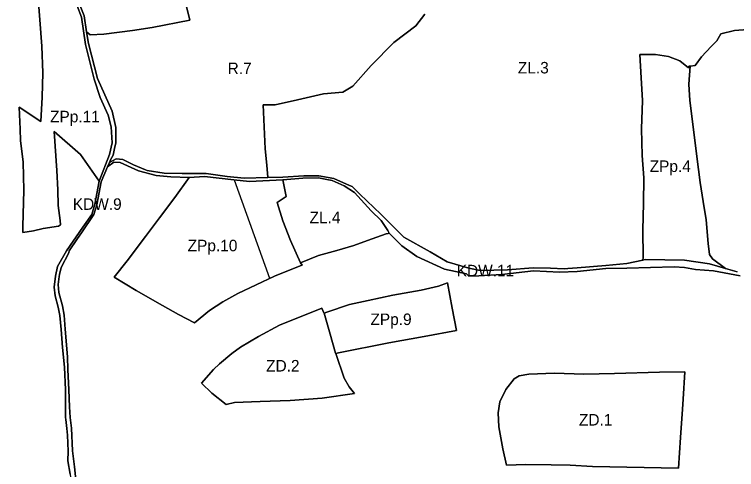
# Model space of a CAD drawing. Extents: x 7418114 to 7422197, y 5546299 to 5548348.
# Drawn here: x 7419820 to 7420446, y 5546631 to 5547025 of the extents above; entities that cross this region are included whole.
import ezdxf

# ---------------------------------------------------------------- set-up
doc = ezdxf.new("R2010")
doc.units = 0
for name, color, linetype in [('linie_lokalizacyjne', 7, 'Continuous'), ('linie_rozgraniczajace', 7, 'Continuous'), ('oznaczenia_przeznaczen', 7, 'Continuous')]:
    doc.layers.add(name, color=color, linetype=linetype)

msp = doc.modelspace()

# ---------------------------------------------------------------- linework, layer by layer
at = {"layer": 'linie_lokalizacyjne'}
msp.add_lwpolyline([(7420041.67, 5546796.53), (7420011.28, 5546881.78)], dxfattribs=at)
at = {"layer": 'linie_rozgraniczajace'}
for points in [[(7419866.28, 5547042.91), (7419867.1, 5547043.21), (7419870.32, 5547044.39), (7419873.48, 5547049.14), (7419876.24, 5547055.72), (7419880.16, 5547059.55), (7419888.8, 5547063.06), (7419894.5, 5547067.18), (7419904.63, 5547076.27), (7419916.45, 5547084.56), (7419931.62, 5547094.6), (7419938.65, 5547100.47), (7419955.53, 5547088.89), (7419972.53, 5547020.52), (7419939.92, 5547014.2), (7419922.63, 5547011.63), (7419898.04, 5547008.4), (7419885.91, 5547007.85), (7419883.01, 5547010.34), (7419880.8, 5547024.17), (7419876.89, 5547034.4), (7419869.75, 5547041.1), (7419866.28, 5547042.91)], [(7420365.05, 5546812.39), (7420365.34, 5546814.53), (7420365.13, 5546838.52), (7420365.57, 5546861.58), (7420365.75, 5546883.8), (7420364.53, 5546902.99), (7420363.96, 5546926.22), (7420364.77, 5546950.76), (7420363.7, 5546970.52), (7420362.55, 5546990.68), (7420362.55, 5546990.68), (7420376.04, 5546990.57), (7420387.25, 5546988.91), (7420397.13, 5546985.1), (7420404.49, 5546979.2), (7420404.8, 5546980.45), (7420405.91, 5546980.54), (7420404.94, 5546964.91), (7420405.7, 5546950.84), (7420408.3, 5546930.35), (7420411.7, 5546902.25), (7420414.68, 5546879.64), (7420417.29, 5546863.26), (7420419.89, 5546847.17), (7420421.68, 5546826.83), (7420422.92, 5546817.13), (7420425.35, 5546813.35), (7420436.66, 5546805.15), (7420422.78, 5546809.01), (7420401.1, 5546812.46), (7420367.15, 5546812.9)], [(7419906.72, 5546797.51), (7419918.11, 5546811.82), (7419934.13, 5546832.93), (7419946.03, 5546849.02), (7419959.33, 5546866.63), (7419971.86, 5546884.03), (7419985.08, 5546884.9), (7419997.9, 5546883.43), (7420010.56, 5546881.87), (7420024.16, 5546880.65), (7420053.14, 5546881.89), (7420055.79, 5546867.64), (7420048.26, 5546862.49), (7420053.02, 5546846.4), (7420059.76, 5546829.38), (7420068.47, 5546810.09), (7420069.64, 5546807.99), (7420068.11, 5546807.33), (7420045.91, 5546798.51), (7420013.9, 5546783.56), (7420000.99, 5546776.21), (7419989.49, 5546768.66), (7419976.35, 5546758.07), (7419962.65, 5546765.35), (7419948.77, 5546773), (7419926.05, 5546786.07)], [(7420048.26, 5546862.49), (7420055.79, 5546867.64), (7420053.14, 5546881.89), (7420070.41, 5546883.55), (7420084, 5546883.64), (7420091.09, 5546882.32), (7420095.8, 5546881.33), (7420106.07, 5546876.93), (7420115.02, 5546870.88), (7420120.94, 5546864.57), (7420129.47, 5546855.14), (7420138.36, 5546846.8), (7420143.92, 5546837.93), (7420145.2, 5546835.86), (7420144.31, 5546835.6), (7420142.44, 5546835.09), (7420126.42, 5546829.27), (7420114.42, 5546825.03), (7420099.8, 5546820.58), (7420084.05, 5546816.29), (7420068.47, 5546810.09), (7420059.76, 5546829.38), (7420053.02, 5546846.4)], [(7419982.44, 5546705.77), (7419991.49, 5546696.97), (7420003.98, 5546687.17), (7420011.2, 5546688.84), (7420033.45, 5546689.74), (7420059.41, 5546690.61), (7420087.07, 5546692.77), (7420115.22, 5546696.83), (7420110.55, 5546702.45), (7420106.29, 5546709.89), (7420098.82, 5546731.5), (7420101.35, 5546731.92), (7420144.89, 5546740.68), (7420175.41, 5546746.11), (7420203.47, 5546751.22), (7420199.7, 5546770.57), (7420195.69, 5546792.55), (7420188.04, 5546789.7), (7420172.95, 5546786.17), (7420148.26, 5546781.86), (7420126.98, 5546777.36), (7420110.72, 5546774), (7420091.14, 5546767.18), (7420088.77, 5546766.33), (7420088.68, 5546766.64), (7420086.92, 5546770.72), (7420050.26, 5546756.02), (7420031.95, 5546746.18), (7420016.26, 5546736.79), (7420008.84, 5546731.36), (7419998.28, 5546722.51), (7419992.88, 5546717.46)], [(7420088.77, 5546766.33), (7420091.14, 5546767.18), (7420110.72, 5546774), (7420126.98, 5546777.36), (7420148.26, 5546781.86), (7420172.95, 5546786.17), (7420188.04, 5546789.7), (7420195.69, 5546792.55), (7420199.7, 5546770.57), (7420203.47, 5546751.22), (7420175.41, 5546746.11), (7420144.89, 5546740.68), (7420101.35, 5546731.92), (7420098.82, 5546731.5), (7420098.71, 5546731.8), (7420093.99, 5546748.17)], [(7419982.44, 5546705.77), (7419992.88, 5546717.46), (7419998.28, 5546722.51), (7420008.84, 5546731.36), (7420016.26, 5546736.79), (7420031.95, 5546746.18), (7420050.26, 5546756.02), (7420086.92, 5546770.72), (7420088.68, 5546766.64), (7420088.77, 5546766.33), (7420093.99, 5546748.17), (7420098.71, 5546731.8), (7420098.82, 5546731.5), (7420106.29, 5546709.89), (7420110.55, 5546702.45), (7420115.22, 5546696.83), (7420087.07, 5546692.77), (7420059.41, 5546690.61), (7420033.45, 5546689.74), (7420011.2, 5546688.84), (7420003.98, 5546687.17), (7419991.49, 5546696.97)], [(7420240.11, 5546667.92), (7420239.63, 5546679.94), (7420241.23, 5546689.33), (7420246.16, 5546700.13), (7420253.58, 5546709.27), (7420257.73, 5546711.89), (7420266.17, 5546713.44), (7420288.55, 5546714.42), (7420313.89, 5546713.56), (7420340.45, 5546714.01), (7420379.52, 5546715.3), (7420401.34, 5546715.46), (7420399.99, 5546691.81), (7420399.37, 5546683.2), (7420397.6, 5546658.65), (7420395.87, 5546631.95), (7420321.28, 5546633.45), (7420301.96, 5546634.42), (7420285.66, 5546634.79), (7420263.57, 5546634.99), (7420246.89, 5546634.62), (7420243.74, 5546648.8)], [(7420240.11, 5546667.92), (7420243.74, 5546648.8), (7420246.89, 5546634.62), (7420263.57, 5546634.99), (7420285.66, 5546634.79), (7420301.96, 5546634.42), (7420321.28, 5546633.45), (7420395.87, 5546631.95), (7420397.6, 5546658.65), (7420399.37, 5546683.2), (7420399.99, 5546691.81), (7420401.34, 5546715.46), (7420379.52, 5546715.3), (7420340.45, 5546714.01), (7420313.89, 5546713.56), (7420288.55, 5546714.42), (7420266.17, 5546713.44), (7420257.73, 5546711.89), (7420253.58, 5546709.27), (7420246.16, 5546700.13), (7420241.23, 5546689.33), (7420239.63, 5546679.94)]]:
    msp.add_lwpolyline(points, close=True, dxfattribs=at)
for points in [[(7420176.23, 5547025.58), (7420168.31, 5547015.71), (7420149.26, 5547001.04), (7420129.64, 5546981.18), (7420113.59, 5546963.34), (7420105.06, 5546958.11), (7420088.41, 5546956.46), (7420065.88, 5546951.36), (7420046.25, 5546947.01), (7420035.99, 5546947.19), (7420037.81, 5546908.93), (7420039.1, 5546894.77), (7420039.92, 5546884.09), (7420019.61, 5546883.55), (7420004.91, 5546884.97), (7419986.53, 5546887.54), (7419965.73, 5546887.45), (7419950.26, 5546887.9), (7419935.59, 5546889.99), (7419933.95, 5546890.59), (7419923.47, 5546895.05), (7419914.48, 5546899.73), (7419908.7, 5546900.3), (7419902.71, 5546897.09), (7419903.7, 5546899.42), (7419905.9, 5546903.46), (7419907.2, 5546909.28), (7419908.29, 5546914.21), (7419908.33, 5546927.39), (7419905.11, 5546941.51), (7419892.52, 5546969.91), (7419884.63, 5547000.22), (7419883.01, 5547010.34), (7419883.01, 5547010.34), (7419885.91, 5547007.85), (7419898.04, 5547008.4), (7419922.63, 5547011.63), (7419939.92, 5547014.2), (7419972.53, 5547020.52), (7419955.53, 5547088.89)], [(7419874.78, 5547032.78), (7419878.44, 5547023.2), (7419882, 5546999.36), (7419889.66, 5546969.26), (7419894.84, 5546953.43), (7419901.59, 5546938.08), (7419904.14, 5546927.9), (7419905.2, 5546914), (7419902.82, 5546904.12), (7419893.77, 5546880.95), (7419877.78, 5546903.94), (7419854.73, 5546924.01), (7419857.1, 5546890.13), (7419857.9, 5546873.34), (7419858.4, 5546859.75), (7419860.02, 5546846.66), (7419860.35, 5546843.04), (7419858.47, 5546841.83), (7419845.25, 5546839.68), (7419837.08, 5546837.67), (7419827.82, 5546836.45), (7419827.71, 5546841.42), (7419828.69, 5546872.98), (7419827.88, 5546897.37), (7419825.8, 5546916.19), (7419825.33, 5546925.83), (7419824.42, 5546945.12), (7419843.29, 5546932.56), (7419844.55, 5546953.57), (7419845.06, 5546974.8), (7419844.11, 5546998.05), (7419840.83, 5547044.02)], [(7419840.83, 5547044.02), (7419844.11, 5546998.05), (7419845.06, 5546974.8), (7419844.55, 5546953.57), (7419843.29, 5546932.56), (7419824.42, 5546945.12), (7419825.33, 5546925.83), (7419825.8, 5546916.19), (7419827.88, 5546897.37), (7419828.69, 5546872.98), (7419827.71, 5546841.42), (7419827.82, 5546836.45), (7419837.08, 5546837.67), (7419845.25, 5546839.68), (7419858.47, 5546841.83), (7419860.35, 5546843.04), (7419860.02, 5546846.66), (7419858.4, 5546859.75), (7419857.9, 5546873.34), (7419857.1, 5546890.13), (7419854.73, 5546924.01), (7419877.78, 5546903.94), (7419893.77, 5546880.95), (7419889.98, 5546860.98), (7419887.46, 5546851.98), (7419879.81, 5546840.93), (7419865.4, 5546820.29), (7419857.82, 5546806.84), (7419855.87, 5546798.48), (7419854.82, 5546788.82), (7419855.76, 5546781.27), (7419858.31, 5546771.66), (7419859.75, 5546764.37), (7419860.96, 5546752.13), (7419862.07, 5546736.6), (7419863.87, 5546719.64), (7419864.55, 5546699.87), (7419864.74, 5546675.78), (7419864.91, 5546674.1), (7419865.88, 5546666.2)], [(7419854.82, 5546788.82), (7419855.87, 5546798.48), (7419857.82, 5546806.84), (7419865.4, 5546820.29), (7419879.81, 5546840.93), (7419887.46, 5546851.98), (7419889.98, 5546860.98), (7419893.77, 5546880.95), (7419902.82, 5546904.12), (7419905.2, 5546914), (7419904.14, 5546927.9), (7419901.59, 5546938.08), (7419894.84, 5546953.43), (7419889.66, 5546969.26), (7419882, 5546999.36), (7419878.44, 5547023.2), (7419874.78, 5547032.78)], [(7419876.89, 5547034.4), (7419880.8, 5547024.17), (7419883.01, 5547010.34), (7419883.01, 5547010.34), (7419884.63, 5547000.22), (7419892.52, 5546969.91), (7419905.11, 5546941.51), (7419908.33, 5546927.39), (7419908.29, 5546914.21), (7419907.2, 5546909.28), (7419905.9, 5546903.46), (7419903.7, 5546899.42), (7419902.71, 5546897.09), (7419901.07, 5546893.28), (7419895.53, 5546880.35), (7419891.69, 5546860.34), (7419889.26, 5546851.8), (7419878.61, 5546835.93), (7419875.19, 5546831.01), (7419867.83, 5546820.42), (7419867.6, 5546818.72), (7419860.88, 5546805.96), (7419859.55, 5546800.03), (7419859.14, 5546798.24), (7419858.26, 5546791.17), (7419858.94, 5546784.2), (7419862.12, 5546772.66), (7419863.48, 5546764.5), (7419864.36, 5546752.52), (7419866.3, 5546728.45), (7419866.8, 5546717.6), (7419867.63, 5546699.76), (7419868.22, 5546685.1), (7419868.59, 5546675.73)], [(7420035.99, 5546947.19), (7420046.25, 5546947.01), (7420065.88, 5546951.36), (7420088.41, 5546956.46), (7420105.06, 5546958.11), (7420113.59, 5546963.34), (7420129.64, 5546981.18), (7420149.26, 5547001.04), (7420168.31, 5547015.71), (7420176.23, 5547025.58)], [(7420471.43, 5547013.51), (7420444.45, 5547011.59), (7420432.61, 5547008.55), (7420429.3, 5547002.69), (7420424.24, 5546997.52), (7420415.98, 5546988.82), (7420410.31, 5546981.1), (7420405.92, 5546980.54), (7420405.91, 5546980.54), (7420404.8, 5546980.45), (7420404.49, 5546979.2), (7420397.13, 5546985.1), (7420387.25, 5546988.91), (7420376.04, 5546990.57), (7420362.55, 5546990.68), (7420362.55, 5546990.68), (7420363.7, 5546970.52), (7420364.77, 5546950.76), (7420363.96, 5546926.22)], [(7420446.86, 5546802.13), (7420436.66, 5546805.15), (7420425.35, 5546813.35), (7420422.92, 5546817.13), (7420421.68, 5546826.83), (7420419.89, 5546847.17), (7420417.29, 5546863.26), (7420414.68, 5546879.64), (7420411.7, 5546902.25), (7420408.3, 5546930.35), (7420405.7, 5546950.84), (7420404.94, 5546964.91), (7420405.91, 5546980.54), (7420405.92, 5546980.54), (7420410.31, 5546981.1), (7420415.98, 5546988.82), (7420424.24, 5546997.52), (7420429.3, 5547002.69), (7420432.61, 5547008.55), (7420444.45, 5547011.59), (7420471.43, 5547013.51)], [(7420363.96, 5546926.22), (7420364.53, 5546902.99), (7420365.75, 5546883.8), (7420365.57, 5546861.58), (7420365.13, 5546838.52), (7420365.34, 5546814.53), (7420365.05, 5546812.39), (7420351.26, 5546809.51), (7420332.85, 5546807.67), (7420308.05, 5546805.54), (7420300, 5546805.04), (7420296.89, 5546804.92), (7420285.07, 5546805.36), (7420269.95, 5546805.68), (7420247.73, 5546804.02), (7420224.09, 5546803.29), (7420214.17, 5546805.48), (7420195.48, 5546810.79), (7420180.6, 5546819.56), (7420157.79, 5546832.25), (7420138.1, 5546852.09), (7420119.81, 5546869.55), (7420112.99, 5546876.36), (7420110.76, 5546877.14), (7420097.2, 5546883.07), (7420084.34, 5546885.53), (7420071.28, 5546885.36), (7420052.93, 5546884.37), (7420039.92, 5546884.09), (7420039.1, 5546894.77), (7420037.81, 5546908.93), (7420035.99, 5546947.19)], [(7420449.38, 5546798.75), (7420426.19, 5546803.13), (7420410.68, 5546804.22), (7420401.03, 5546806.08), (7420392.17, 5546806.44), (7420351.27, 5546805.53), (7420332.86, 5546805.1), (7420308.06, 5546802.49), (7420292.74, 5546801.88), (7420270.15, 5546803.21), (7420242.77, 5546800.03), (7420223, 5546798.81), (7420214.14, 5546798.38), (7420212.09, 5546800.58), (7420193.19, 5546804.57), (7420169.25, 5546815.65), (7420156.19, 5546824.71), (7420145.2, 5546835.86), (7420143.92, 5546837.93), (7420138.36, 5546846.8), (7420129.47, 5546855.14), (7420120.94, 5546864.57), (7420115.02, 5546870.88), (7420106.07, 5546876.93), (7420095.8, 5546881.33), (7420091.09, 5546882.32), (7420084, 5546883.64), (7420070.41, 5546883.55), (7420053.14, 5546881.89), (7420024.16, 5546880.65), (7420010.56, 5546881.87), (7419997.9, 5546883.43), (7419985.08, 5546884.9), (7419971.86, 5546884.03), (7419956.1, 5546884.52), (7419943.21, 5546885.79), (7419928.02, 5546889.78), (7419912.13, 5546896.98), (7419906.42, 5546897.44), (7419901.07, 5546893.28), (7419902.71, 5546897.09), (7419908.7, 5546900.3), (7419914.48, 5546899.73), (7419923.47, 5546895.05), (7419933.95, 5546890.59), (7419935.59, 5546889.99), (7419950.26, 5546887.9), (7419965.73, 5546887.45), (7419986.53, 5546887.54), (7420004.91, 5546884.97), (7420019.61, 5546883.55), (7420039.92, 5546884.09), (7420052.93, 5546884.37), (7420071.28, 5546885.36), (7420084.34, 5546885.53), (7420097.2, 5546883.07), (7420110.76, 5546877.14), (7420112.99, 5546876.36), (7420119.81, 5546869.55), (7420138.1, 5546852.09), (7420157.79, 5546832.25), (7420180.6, 5546819.56), (7420195.48, 5546810.79), (7420214.17, 5546805.48), (7420224.09, 5546803.29), (7420247.73, 5546804.02), (7420269.95, 5546805.68), (7420285.07, 5546805.36), (7420296.89, 5546804.92), (7420300, 5546805.04), (7420308.05, 5546805.54), (7420332.85, 5546807.67), (7420351.26, 5546809.51), (7420365.05, 5546812.39), (7420367.15, 5546812.9), (7420401.1, 5546812.46), (7420422.78, 5546809.01), (7420436.66, 5546805.15), (7420446.86, 5546802.13)], [(7419858.26, 5546791.17), (7419859.14, 5546798.24), (7419859.55, 5546800.03), (7419860.88, 5546805.96), (7419867.6, 5546818.72), (7419867.83, 5546820.42), (7419875.19, 5546831.01), (7419878.61, 5546835.93), (7419889.26, 5546851.8), (7419891.69, 5546860.34), (7419895.53, 5546880.35), (7419901.07, 5546893.28), (7419906.42, 5546897.44), (7419912.13, 5546896.98), (7419928.02, 5546889.78), (7419943.21, 5546885.79), (7419956.1, 5546884.52), (7419971.86, 5546884.03), (7419959.33, 5546866.63), (7419946.03, 5546849.02), (7419934.13, 5546832.93), (7419918.11, 5546811.82), (7419906.72, 5546797.51), (7419926.05, 5546786.07), (7419948.77, 5546773), (7419962.65, 5546765.35), (7419976.35, 5546758.07), (7419989.49, 5546768.66), (7420000.99, 5546776.21), (7420013.9, 5546783.56), (7420045.91, 5546798.51), (7420068.11, 5546807.33), (7420069.64, 5546807.99), (7420068.47, 5546810.09), (7420084.05, 5546816.29), (7420099.8, 5546820.58), (7420114.42, 5546825.03), (7420126.42, 5546829.27), (7420142.44, 5546835.09), (7420144.31, 5546835.6), (7420145.2, 5546835.86), (7420156.19, 5546824.71), (7420169.25, 5546815.65), (7420193.19, 5546804.57), (7420212.09, 5546800.58), (7420214.14, 5546798.38), (7420223, 5546798.81), (7420242.77, 5546800.03), (7420270.15, 5546803.21), (7420292.74, 5546801.88), (7420308.06, 5546802.49), (7420332.86, 5546805.1), (7420351.27, 5546805.53), (7420392.17, 5546806.44), (7420401.03, 5546806.08), (7420410.68, 5546804.22), (7420426.19, 5546803.13), (7420449.38, 5546798.75)], [(7419868.7, 5546626.77), (7419866.77, 5546638.42), (7419866.94, 5546646.66), (7419866.48, 5546660.67), (7419865.88, 5546666.2), (7419864.91, 5546674.1), (7419864.74, 5546675.78), (7419864.55, 5546699.87), (7419863.87, 5546719.64), (7419862.07, 5546736.6), (7419860.96, 5546752.13), (7419859.75, 5546764.37), (7419858.31, 5546771.66), (7419855.76, 5546781.27), (7419854.82, 5546788.82)], [(7419875.32, 5546604.84), (7419872.34, 5546633.2), (7419870.84, 5546646.94), (7419869.74, 5546666.6), (7419868.59, 5546675.73), (7419868.22, 5546685.1), (7419867.63, 5546699.76), (7419866.8, 5546717.6), (7419866.3, 5546728.45), (7419864.36, 5546752.52), (7419863.48, 5546764.5), (7419862.12, 5546772.66), (7419858.94, 5546784.2), (7419858.26, 5546791.17)], [(7419868.59, 5546675.73), (7419869.74, 5546666.6), (7419870.84, 5546646.94), (7419872.34, 5546633.2), (7419875.32, 5546604.84)], [(7419865.88, 5546666.2), (7419866.48, 5546660.67), (7419866.94, 5546646.66), (7419866.77, 5546638.42), (7419868.7, 5546626.77), (7419869.62, 5546619.26), (7419870.47, 5546602.72), (7419871.85, 5546579.92), (7419874.28, 5546562.95), (7419876.97, 5546543.32), (7419880.2, 5546517.21), (7419883.54, 5546497.63), (7419885.88, 5546486.64), (7419889.62, 5546466.02), (7419891.75, 5546451.67), (7419865.22, 5546449.75), (7419854.72, 5546448.54), (7419852.03, 5546447.76), (7419850.29, 5546458.18), (7419845.6, 5546486.47), (7419842.35, 5546506.08), (7419799.96, 5546502.72)]]:
    msp.add_lwpolyline(points, dxfattribs=at)

# ---------------------------------------------------------------- texts
at = {"layer": 'oznaczenia_przeznaczen'}
for s, p in [('R.7', (7420005.19, 5546973.69)), ('ZL.3', (7420256.72, 5546974.27)), ('ZPp.11', (7419851.28, 5546931.85)), ('ZPp.4', (7420370.96, 5546888.83)), ('KDW.9', (7419871, 5546855.97)), ('ZL.4', (7420076.2, 5546844.37)), ('ZPp.10', (7419970.55, 5546820.03)), ('KDW.11', (7420203.72, 5546798.29)), ('ZPp.9', (7420128.95, 5546756.06)), ('ZD.2', (7420038.54, 5546715.76)), ('ZD.1', (7420309.68, 5546668.9))]:
    msp.add_text(s, height=10, dxfattribs=at).set_placement(p)

doc.saveas('drawing.dxf')
